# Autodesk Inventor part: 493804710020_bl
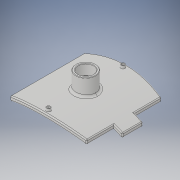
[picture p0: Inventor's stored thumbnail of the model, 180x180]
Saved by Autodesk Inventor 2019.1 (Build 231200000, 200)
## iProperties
Created: 2017-10
Part Number: 493804710020_bl
Material: Generic
Description: PLASSON BRANCH SADDLE 450-800 x 2''
Document SubType Name: Modeling
Designer: KIM
Density: 1 g/cm^3
Appearance: Default
Author: KIM
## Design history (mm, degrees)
derived "493804-2.ipt"
feature "Solid1::493804-2.ipt" dims "ScaleForDerivedMember" = 10
tag "TaggingFeature1"
body "Solid1"
other parameters: "d2" = 283.5 [user parameter], "d3" = 306 [user parameter], "d4" = 0 [user parameter], "d5" = 315 [user parameter], "d6" = 76.5 [user parameter], "d7" = 0 [user parameter], "d8" = 137.7 [user parameter], "d10" = 0 [user parameter], "d11" = 4 [user parameter], "d12" = 425.6 [user parameter], "d13" = 14 [user parameter], "d14" = 137.7 [user parameter], "d16" = 5 deg [user parameter], "d18" = 4 [user parameter], "d19" = 14 [user parameter], "d20" = 0 [user parameter], "d21" = 3 [user parameter], "d22" = 0 [user parameter], "d23" = 477 [user parameter], "d24" = 73.6528 [user parameter], "d25" = 16 [user parameter], "d26" = 56.656 [user parameter], "d28" = 0 [user parameter], "d29" = 9.6 [user parameter], "d31" = 0 [user parameter], "d32" = 53.9 [user parameter], "d33" = 0 [user parameter], "d34" = 8 [user parameter], "d35" = 1.6 [user parameter], "d36" = -38.5 [user parameter], "d38" = 53.8232 [user parameter], "d40" = 0 [user parameter], "d41" = 832 [user parameter], "d_1" = 114.1 [user parameter], "B_" = 315 [user parameter], "H_" = 77 [user parameter], "L_" = 306 [user parameter], "x_" = -26.886 [user parameter], "D_" = 16 [user parameter], "H1" = 103.886 [user parameter], "G_" = 56.656 [user parameter]
